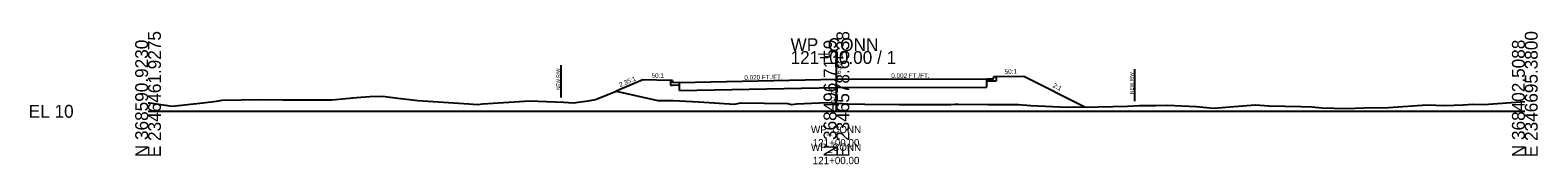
# Model space of a CAD drawing. Extents: x -26 to 2345577, y -10 to 367097.
# Drawn here: x 974.3 to 1302.8, y 7988.5 to 8017.3 of the extents above; entities that cross this region are included whole.
import ezdxf

# ---------------------------------------------------------------- set-up
doc = ezdxf.new("R2010")
doc.units = 0
for name, color, linetype in [('RD_GPK_XS_Cell', 7, 'Continuous'), ('RD_XS_Base', 7, 'Continuous'), ('RD_XS_CurbTop', 7, 'Continuous'), ('RD_XS_EarthShd', 7, 'Continuous'), ('RD_XS_ExGround', 7, 'Continuous'), ('RD_XS_NewRW', 7, 'Continuous'), ('RD_XS_Pave', 7, 'Continuous'), ('RD_XS_TieSlope', 7, 'Continuous'), ('RD_XS_TX_Elev_EX', 7, 'Continuous'), ('RD_XS_TX_Elev_PR', 7, 'Continuous'), ('RD_XS_TX_Slope', 7, 'Continuous'), ('RD_XS_TX_Station', 7, 'Continuous'), ('RD_XS_TX_TOC', 7, 'Continuous')]:
    doc.layers.add(name, color=color, linetype=linetype)

msp = doc.modelspace()

# ---------------------------------------------------------------- linework, layer by layer
at = {"layer": 'RD_GPK_XS_Cell'}
for p, q in [((1150, 8000), (1150, 8013.13)), ((1000, 8000), (1150, 8000)), ((1150, 8000), (1300, 8000))]:
    msp.add_line(p, q, dxfattribs=at)
at = {"layer": 'RD_XS_Base'}
for p, q in [((1113.81, 8006.71), (1113.81, 8005.71)), ((1182.8, 8006.55), (1182.8, 8007.05)), ((1184.3, 8006.55), (1182.8, 8006.55)), ((1182.8, 8005.27), (1182.8, 8006.55)), ((1184.8, 8006.55), (1184.3, 8006.55)), ((1184.8, 8007.55), (1184.8, 8006.55)), ((1113.81, 8005.71), (1114.31, 8005.71)), ((1114.31, 8005.71), (1115.81, 8005.79)), ((1115.81, 8005.79), (1115.81, 8006.29)), ((1115.81, 8004.51), (1115.81, 8005.79)), ((1115.81, 8004.51), (1150.02, 8005.2)), ((1150.02, 8005.2), (1182.8, 8005.27))]:
    msp.add_line(p, q, dxfattribs=at)
at = {"layer": 'RD_XS_CurbTop'}
for p, q in [((1114.31, 8006.71), (1113.81, 8006.71)), ((1114.39, 8006.21), (1114.31, 8006.71)), ((1182.8, 8007.07), (1182.8, 8007.05)), ((1182.8, 8007.05), (1184.22, 8007.05)), ((1184.22, 8007.05), (1184.3, 8007.55)), ((1184.3, 8007.55), (1184.8, 8007.55)), ((1115.81, 8006.29), (1114.39, 8006.21)), ((1115.81, 8006.31), (1115.81, 8006.29))]:
    msp.add_line(p, q, dxfattribs=at)
at = {"layer": 'RD_XS_EarthShd'}
for p, q in [((1113.81, 8006.71), (1107.81, 8006.83)), ((1184.8, 8007.55), (1190.8, 8007.67))]:
    msp.add_line(p, q, dxfattribs=at)
at = {"layer": 'RD_XS_ExGround'}
msp.add_lwpolyline([(1000, 8001.86), (1000.35, 8001.81), (1005.27, 8001.15), (1011.94, 8001.85), (1014.93, 8002.21), (1016.15, 8002.44), (1024.38, 8002.55), (1029.28, 8002.5), (1035.25, 8002.48), (1036.65, 8002.51), (1040.03, 8002.52), (1045.39, 8003.04), (1048.34, 8003.23), (1051.11, 8003.3), (1054.42, 8002.86), (1057.61, 8002.51), (1058.79, 8002.37), (1069.89, 8001.64), (1071.76, 8001.51), (1072.86, 8001.6), (1083.22, 8002.27), (1090.52, 8002.02), (1092.68, 8001.84), (1096.31, 8002.35), (1097.51, 8002.59), (1102.01, 8004.36), (1111.09, 8002.36), (1114.42, 8002.34), (1120.01, 8002.1), (1127.81, 8001.58), (1129.17, 8001.88), (1139.31, 8001.68), (1140.2, 8001.51), (1141.27, 8001.62), (1147.94, 8001.94), (1150, 8001.79), (1152.47, 8001.61), (1156.16, 8001.59), (1163.65, 8001.49), (1166.64, 8001.5), (1174.93, 8001.48), (1175.89, 8001.53), (1176.54, 8001.52), (1183, 8001.49), (1188.61, 8001.5), (1189.07, 8001.45), (1189.69, 8001.49), (1192.39, 8001.29), (1200.27, 8000.87), (1201.56, 8000.94), (1203.77, 8000.91), (1213.39, 8001.1), (1216.02, 8001.26), (1219.56, 8001.23), (1222.17, 8001.32), (1228.4, 8001.06), (1232.21, 8000.66), (1236.67, 8001.07), (1241.33, 8001.44), (1244.22, 8001.19), (1251.22, 8001.04), (1253.59, 8000.99), (1255.86, 8000.73), (1261.1, 8000.61), (1264.97, 8000.79), (1270.33, 8000.8), (1278.66, 8001.39), (1282.58, 8001.26), (1286.54, 8001.43), (1288.67, 8001.53), (1291.07, 8001.49), (1300, 8002.11)], dxfattribs=at)
at = {"layer": 'RD_XS_NewRW'}
for p, q in [((1090, 8003.03), (1090, 8010.03)), ((1215, 8002.2), (1215, 8009.2))]:
    msp.add_line(p, q, dxfattribs=at)
at = {"layer": 'RD_XS_Pave'}
for p, q in [((1115.81, 8006.31), (1150, 8006.99)), ((1150, 8006.99), (1182.8, 8007.07))]:
    msp.add_line(p, q, dxfattribs=at)
at = {"layer": 'RD_XS_TieSlope'}
for p, q in [((1107.81, 8006.83), (1102.01, 8004.36)), ((1190.8, 8007.67), (1204.3, 8000.92))]:
    msp.add_line(p, q, dxfattribs=at)

# ---------------------------------------------------------------- texts
at = {"layer": 'RD_GPK_XS_Cell'}
for s, p in [('E 2346461.9275', (1002.8, 7990)), ('E 2346578.6538', (1152.8, 7990)), ('E 2346695.3800', (1302.8, 7990)), ('N 368590.9230', (1000, 7990)), ('N 368496.7159', (1150, 7990)), ('N 368402.5088', (1300, 7990))]:
    msp.add_text(s, height=2.8, rotation=90, dxfattribs=at).set_placement(p)
for s, p in [('WP_CONN', (1140, 8013.13)), ('121+00.00 / 1', (1140, 8010.33)), ('EL 10', (974, 7998.6))]:
    msp.add_text(s, height=2.8, dxfattribs=at).set_placement(p)
at = {"layer": 'RD_XS_NewRW'}
for p in [(1089.75, 8004.62), (1214.74, 8003.79)]:
    msp.add_text('NEW R/W ', height=0.75, rotation=90, dxfattribs=at).set_placement(p)
at = {"layer": 'RD_XS_TX_Elev_EX'}
msp.add_text('11.79', height=1, rotation=90, dxfattribs=at).set_placement((1149.82, 8001.83))
at = {"layer": 'RD_XS_TX_Elev_PR'}
for s, rotation, p in [(' 16.99', 90, (1151, 8006.99)), ('2.35:1', 23.0502, (1102.88, 8005.26)), ('50:1', 358.8542, (1109.7, 8007.31)), ('50:1', 1.1458, (1186.66, 8008.14)), ('2:1', 333.4349, (1197.05, 8005.31))]:
    msp.add_text(s, height=1, rotation=rotation, dxfattribs=at).set_placement(p)
at = {"layer": 'RD_XS_TX_Slope'}
for s, rotation, p in [('0.020 FT./FT.', 1.1458, (1129.94, 8006.84)), ('0.002 FT./FT.', 0.1283, (1161.95, 8007.27))]:
    msp.add_text(s, height=1, rotation=rotation, dxfattribs=at).set_placement(p)
at = {"layer": 'RD_XS_TX_Station'}
for s, p in [('WP_CONN', (1144.45, 7995.24)), ('121+00.00', (1144.83, 7992.34)), ('WP_CONN', (1144.45, 7991.38)), ('121+00.00', (1144.83, 7988.48))]:
    msp.add_text(s, height=1.6, dxfattribs=at).set_placement(p)
at = {"layer": 'RD_XS_TX_TOC'}
for s, p in [('TOCLT', (1114.36, 8006.66)), ('TOCRT', (1184.02, 8007.5))]:
    msp.add_text(s, height=0.05, dxfattribs=at).set_placement(p)

doc.saveas('drawing.dxf')
